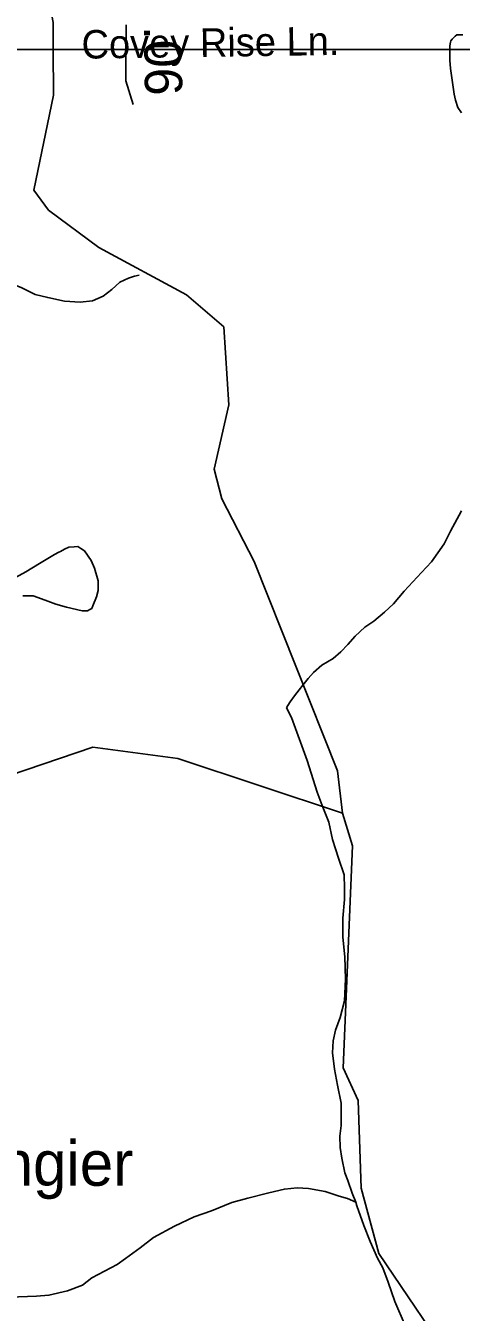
# Model space of a CAD drawing. Extents: x 2001466 to 2224147, y 644118 to 847247.
# Drawn here: x 2074618 to 2076073, y 653960 to 658253 of the extents above; entities that cross this region are included whole.
import ezdxf

# ---------------------------------------------------------------- set-up
doc = ezdxf.new("R2010")
doc.units = 0
for name, color, linetype in [('Exist Aviation Public Landing Strip Label', 7, 'Continuous'), ('Exist Hydrographic Creek Single Shore', 7, 'Continuous'), ('Exist Hydrographic Misc Water Feature', 7, 'Continuous'), ('Exist Road Secondary Mileage Hundredths English Label', 7, 'Continuous'), ('Exist Road Secondary Type 51 Attributed', 7, 'Continuous'), ('Exist Road Secondary Type 51 Label', 7, 'Continuous'), ('Map Preparation Inset Cut Line', 7, 'Continuous')]:
    doc.layers.add(name, color=color, linetype=linetype)

msp = doc.modelspace()

# ---------------------------------------------------------------- linework, layer by layer
at = {"layer": 'Exist Hydrographic Creek Single Shore'}
for points in [[(2074710.2, 658173.9), (2074709.8, 658263.5), (2074658.9, 658536.8), (2074608.9, 658646.1), (2074431.5, 658772.1)], [(2075676.8, 655625.8), (2075659.8, 655767.2), (2075381.8, 656465.1), (2075272.9, 656674), (2075247.9, 656772.9), (2075296.9, 656988.4), (2075279.8, 657248), (2075154.8, 657355.5), (2074861.9, 657512.4), (2074694.8, 657637.1), (2074644.8, 657703.8), (2074710.8, 658020.6), (2074710.2, 658173.9)], [(2078595, 653007.8), (2078482.9, 652883.9), (2078284.7, 652790.7), (2078217.8, 652792.1), (2078100.7, 652840.4), (2077933.8, 652981.6), (2077708.7, 653048.4), (2077057.6, 653380), (2076532.7, 653443.1), (2076315.8, 653559.1), (2076065.8, 653761), (2075797.8, 654156.8), (2075738.8, 654374.6), (2075728.7, 654666.8), (2075678.9, 654776), (2075709.8, 655516.8), (2075676.8, 655625.8)]]:
    msp.add_lwpolyline(points, dxfattribs=at)
at = {"layer": 'Exist Hydrographic Misc Water Feature'}
for points in [[(2076034.8, 658138.2), (2076034.6, 658166.2), (2076034.6, 658184.1), (2076036.5, 658192.3), (2076036.7, 658198.4), (2076038.5, 658202.2), (2076042.6, 658208.4), (2076052.3, 658218.3), (2076058.4, 658222.3), (2076064.6, 658222.6), (2076072.6, 658222.6), (2076078.5, 658222.5)], [(2076073.4, 657962.5), (2076061.1, 657980.5), (2076053.3, 658004.4), (2076049.4, 658024.5), (2076036.9, 658110.4), (2076034.8, 658138.2)], [(2074435.6, 657454.2), (2074445.9, 657452.2), (2074477.9, 657432.4), (2074511.7, 657416.7), (2074553.6, 657399), (2074605.6, 657377.8), (2074649.7, 657356.1), (2074691.8, 657346), (2074747.5, 657334.3), (2074799.6, 657330.5), (2074841.7, 657334.7), (2074877.3, 657350.7), (2074905.4, 657372.9), (2074933.1, 657397.1), (2074961, 657411.1), (2074981.1, 657417.4), (2074997.1, 657421)], [(2076073.6, 656634.5), (2076037.5, 656566.6), (2076015.8, 656524.5), (2075973.7, 656464.3), (2075940.1, 656428.4), (2075882.3, 656366.2), (2075846.2, 656324.2), (2075816.5, 656295.9), (2075781, 656266), (2075750.9, 656245.8), (2075719.1, 656215.8), (2075694.7, 656187.8), (2075670.7, 656163.4), (2075645, 656141.4), (2075607.3, 656119.1), (2075579, 656095.4), (2075561.2, 656075.4), (2075543.5, 656053), (2075531.4, 656037.3), (2075515.5, 656017), (2075501.5, 655997.2), (2075493.5, 655985.1), (2075489.6, 655977.1)], [(2074714.1, 656488.5), (2074664.5, 656458.3), (2074618.6, 656430.4), (2074584.5, 656412)], [(2074608.7, 656350.3), (2074642.8, 656350.5), (2074682.7, 656336.3), (2074718.8, 656322.7), (2074754.5, 656312.8), (2074807, 656300.8), (2074824.8, 656301), (2074832.8, 656305), (2074839, 656309), (2074842.9, 656316.9), (2074854.6, 656347.2), (2074860.3, 656369), (2074860.3, 656386.8), (2074860.7, 656401), (2074848.4, 656443), (2074836.3, 656468.8), (2074814.4, 656500.9), (2074802.1, 656508.8), (2074792, 656514.8), (2074780.1, 656514.6), (2074761.9, 656512.9), (2074748.1, 656506.4), (2074734, 656498.4), (2074728.3, 656496.5), (2074714.1, 656488.5)], [(2075489.6, 655977.1), (2075505.6, 655945.2), (2075558.1, 655801.3), (2075592.3, 655695.6), (2075608.3, 655651.3), (2075630.9, 655595.6)], [(2075676.8, 655625.8), (2075125.9, 655807.6), (2074842.9, 655846.1), (2074451.8, 655713)], [(2075630.9, 655595.6), (2075643, 655537.8), (2075663.3, 655475.9), (2075681.5, 655419.6), (2075683.6, 655375.9), (2075683.6, 655337.8), (2075677.4, 655275.8), (2075677.9, 655211.7), (2075684.2, 655145.8), (2075686.5, 655072.1), (2075682.6, 654999.7), (2075668.8, 654943.7), (2075653, 654902), (2075644.8, 654865.9), (2075643.4, 654825.9), (2075649.1, 654771.9), (2075659.4, 654718.1), (2075671.9, 654657.8), (2075671.9, 654584), (2075668, 654548), (2075668.4, 654509.8), (2075674.4, 654474.1), (2075684.6, 654425.9), (2075694.3, 654400), (2075708.6, 654358.2), (2075720.5, 654328)], [(2074563.8, 654010.4), (2074653.8, 654014.6), (2074695.9, 654017.2), (2074757.6, 654031.4), (2074807.8, 654051.3), (2074839.4, 654075.3), (2074923.3, 654119.8), (2074951.4, 654139.9), (2075001, 654175.8), (2075045.1, 654210.1), (2075115.2, 654248.1), (2075181, 654278.3), (2075238.8, 654298.7), (2075306.7, 654326.9), (2075360.6, 654341.1), (2075430.4, 654359.3), (2075482.4, 654371.3), (2075524.5, 654375.5), (2075562.8, 654373.7), (2075618.6, 654363.7), (2075664.7, 654348.2), (2075692.8, 654339.9), (2075720.5, 654328)], [(2075720.5, 654328), (2075724.6, 654316), (2075747.2, 654250.1), (2075769.1, 654196.5), (2075793.5, 654140.5), (2075811.5, 654108.6), (2075829.4, 654060.8), (2075851.5, 653996.6), (2075885.8, 653916.8), (2075914.3, 653870.7), (2075939.9, 653831.1), (2075960.2, 653804.9), (2076002.7, 653745.4), (2076048.6, 653687.3), (2076070.5, 653661.2), (2076106.8, 653623.3)]]:
    msp.add_lwpolyline(points, dxfattribs=at)
at = {"layer": 'Exist Road Secondary Type 51 Attributed'}
msp.add_lwpolyline([(2074953.6, 658255.4), (2074952.5, 658069.5), (2074976.8, 657990.2)], dxfattribs=at)
at = {"layer": 'Map Preparation Inset Cut Line'}
for p, q in [((2074710.2, 658173.9), (2074173.7, 658173.9)), ((2076402.2, 658173.9), (2074710.2, 658173.9))]:
    msp.add_line(p, q, dxfattribs=at)

# ---------------------------------------------------------------- texts
at = {"layer": 'Exist Aviation Public Landing Strip Label'}
msp.add_text('Fuquay- Angier', height=150, dxfattribs=at).set_placement((2073605.9, 654382.5))
at = {"layer": 'Exist Road Secondary Mileage Hundredths English Label'}
msp.add_text('.06', height=125, rotation=270.8271, dxfattribs=at).set_placement((2075013.3, 658251.4))
at = {"layer": 'Exist Road Secondary Type 51 Label'}
msp.add_text('Covey Rise Ln.', height=95, rotation=0.8326, dxfattribs=at).set_placement((2074805.3, 658142.8))

doc.saveas('drawing.dxf')
